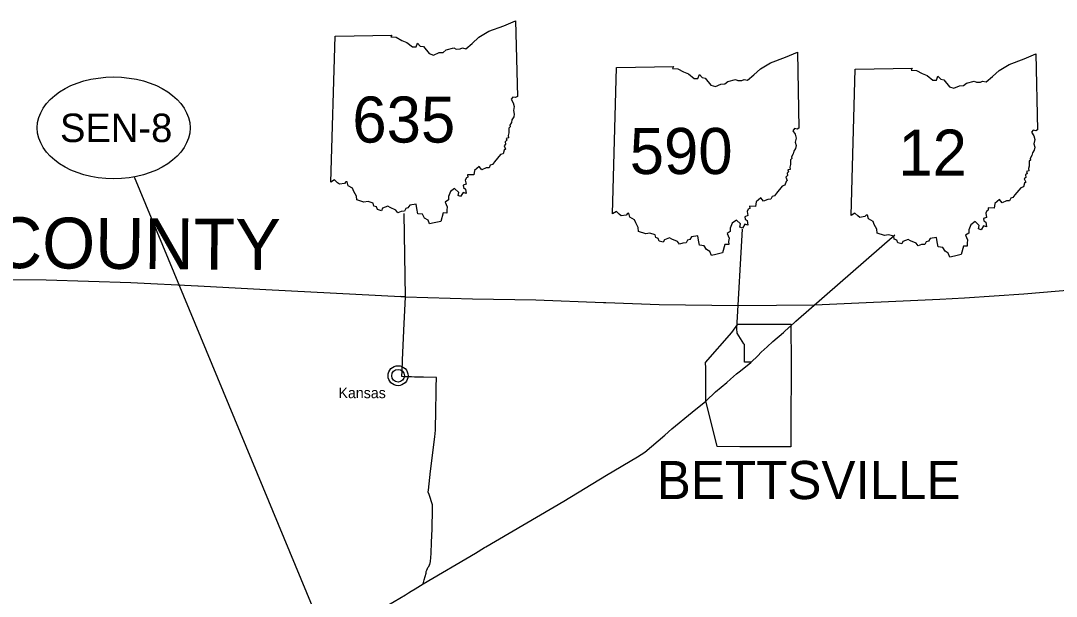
# Model space of a CAD drawing. Extents: x 0 to 882, y 0 to 440.
# Drawn here: x 198.3 to 300, y 305.2 to 361.8 of the extents above; entities that cross this region are included whole.
import ezdxf

# ---------------------------------------------------------------- set-up
doc = ezdxf.new("R2010")
doc.units = 0
for name, color, linetype in [('DV_X_Corp_Line', 7, 'Continuous'), ('GM_X_Adjacent_County_Text', 7, 'Continuous'), ('GM_X_Corporation_Text', 7, 'Continuous'), ('GM_X_County', 7, 'Continuous'), ('GM_X_State_Route', 7, 'Continuous'), ('PV_P_Text', 7, 'Continuous'), ('SH_Data', 7, 'Continuous')]:
    doc.layers.add(name, color=color, linetype=linetype)

msp = doc.modelspace()

# ---------------------------------------------------------------- linework, layer by layer
at = {"layer": 'DV_X_Corp_Line'}
msp.add_lwpolyline([(268.15, 331.12), (268.71, 331.93), (273.95, 331.93), (273.94, 331.71), (273.95, 328.22), (273.93, 321.61), (273.92, 319.86), (268.93, 319.88), (266.71, 319.91), (265.57, 324.39), (265.57, 327.61), (265.56, 328.17)], close=True, dxfattribs=at)
for radius in [0.982, 0.623]:
    msp.add_circle((235.37, 326.86), radius, dxfattribs=at)
at = {"layer": 'GM_X_County'}
msp.add_lwpolyline([(194.2, 336.33), (200.83, 336.27), (209.14, 336.02), (215.71, 335.69), (215.76, 335.68), (222.4, 335.32), (235.64, 334.64), (236.1, 334.62), (242.69, 334.42), (248.88, 334.31), (255.53, 334.06), (255.76, 334.05), (260.99, 333.86), (268.76, 333.76), (276.28, 333.83), (288.57, 334.37), (290.97, 334.51), (296.79, 334.89), (301.81, 335.33)], dxfattribs=at)
at = {"layer": 'GM_X_State_Route'}
msp.add_line((236.1, 334.62), (235.98, 342.8), dxfattribs=at)
for points in [[(268.63, 331.49), (268.63, 331.51), (269.18, 341.26)], [(274.42, 332.22), (284.15, 340.7)], [(235.74, 326.91), (235.76, 327.2), (235.78, 327.6), (235.78, 327.71), (235.79, 328), (235.81, 328.39), (235.92, 331.3), (236.1, 334.62), (235.64, 334.64)], [(270.03, 328.19), (269.39, 328.2), (269.39, 329.84), (269.38, 329.91), (269.33, 329.99), (268.66, 331.04), (268.63, 331.49)], [(271.62, 329.71), (272.16, 330.21), (273.21, 331.11), (273.81, 331.66), (273.85, 331.69)], [(273.85, 331.69), (274.39, 332.18), (274.42, 332.22)], [(270.68, 328.82), (271.03, 329.17), (271.62, 329.71)], [(270.03, 328.19), (270.68, 328.82)], [(268, 326.51), (268.61, 327.03), (268.86, 327.23), (269.31, 327.6)], [(269.31, 327.6), (270, 328.16), (270.03, 328.19)], [(239.12, 325.72), (239.15, 326.67), (237.87, 326.71), (237.59, 326.71), (237.29, 326.72), (236.98, 326.73), (236.68, 326.74), (236.41, 326.75), (236.08, 326.76), (235.74, 326.77), (235.74, 326.91)], [(265.63, 324.4), (266.53, 325.26), (267.64, 326.2), (268, 326.51)], [(237.85, 306.39), (237.92, 306.79), (238.12, 307.45), (238.14, 307.6), (238.18, 307.75), (238.26, 307.91), (238.29, 308), (238.38, 308.09), (238.43, 308.19), (238.49, 308.3), (238.57, 308.59), (238.63, 309.39), (238.65, 310.51), (238.71, 311.77), (238.75, 313.76), (238.75, 314.18), (238.7, 314.37), (238.49, 314.99), (238.41, 315.19), (238.34, 315.4), (238.34, 315.46), (238.35, 315.6), (238.57, 317.48), (238.97, 320.85), (239.03, 321.5), (239.05, 322.02), (239.08, 322.99), (239.12, 325.65), (239.12, 325.72)], [(243.86, 309.96), (243.97, 310.03), (251.64, 314.54), (255.82, 317.07), (258.88, 318.87), (259.61, 319.34), (261.55, 321), (262.26, 321.65), (264.25, 323.26), (265.59, 324.36), (265.63, 324.4)], [(236.65, 305.67), (237.06, 305.92), (237.85, 306.39), (242.96, 309.4), (243.86, 309.96)], [(218.84, 295.17), (218.85, 295.17), (221.01, 296.41), (221.46, 296.67), (228.35, 300.67), (232.56, 303.24), (234.98, 304.67), (236.1, 305.33), (236.39, 305.51), (236.65, 305.67)]]:
    msp.add_lwpolyline(points, dxfattribs=at)
at = {"layer": 'PV_P_Text'}
for p, q in [((228.77, 345.88), (229.18, 360.24)), ((228.77, 345.88), (229.18, 360.24)), ((256.43, 342.78), (256.83, 357.14)), ((256.43, 342.78), (256.83, 357.14)), ((279.86, 342.62), (280.26, 356.98)), ((279.86, 342.62), (280.26, 356.98))]:
    msp.add_line(p, q, dxfattribs=at)
for points in [[(229.18, 360.24), (234.75, 360.33), (234.66, 360.16), (235.19, 360.12), (235.75, 359.82), (236.22, 359.62), (236.8, 359.17), (237.14, 359.17), (237.29, 359.55), (237.55, 359.26), (237.87, 359.21), (238.41, 358.52), (238.86, 358.37), (239.4, 358.61), (239.8, 358.64), (240.09, 358.88), (240.85, 359.08), (241.07, 358.96), (241.47, 358.98), (241.68, 359.07), (242.03, 358.99), (242.65, 359.51), (243.29, 360.13), (244.28, 360.71), (245.75, 361.26), (246.91, 361.75), (247.08, 354.3)], [(229.18, 360.24), (234.75, 360.33), (234.66, 360.16), (235.19, 360.12), (235.75, 359.82), (236.22, 359.62), (236.8, 359.17), (237.14, 359.17), (237.29, 359.55), (237.55, 359.26), (237.87, 359.21), (238.41, 358.52), (238.86, 358.37), (239.4, 358.61), (239.8, 358.64), (240.09, 358.88), (240.85, 359.08), (241.07, 358.96), (241.47, 358.98), (241.68, 359.07), (242.03, 358.99), (242.65, 359.51), (243.29, 360.13), (244.28, 360.71), (245.75, 361.26), (246.91, 361.75), (247.08, 354.3)], [(256.83, 357.14), (262.41, 357.24), (262.32, 357.06), (262.85, 357.03), (263.4, 356.72), (263.88, 356.53), (264.45, 356.07), (264.8, 356.08), (264.95, 356.45), (265.21, 356.16), (265.53, 356.11), (266.07, 355.42), (266.52, 355.27), (267.05, 355.51), (267.46, 355.55), (267.75, 355.78), (268.51, 355.98), (268.73, 355.86), (269.13, 355.88), (269.34, 355.97), (269.69, 355.89), (270.31, 356.42), (270.95, 357.03), (271.93, 357.61), (273.4, 358.16), (274.57, 358.66), (274.73, 351.2)], [(256.83, 357.14), (262.41, 357.24), (262.32, 357.06), (262.85, 357.03), (263.4, 356.72), (263.88, 356.53), (264.45, 356.07), (264.8, 356.08), (264.95, 356.45), (265.21, 356.16), (265.53, 356.11), (266.07, 355.42), (266.52, 355.27), (267.05, 355.51), (267.46, 355.55), (267.75, 355.78), (268.51, 355.98), (268.73, 355.86), (269.13, 355.88), (269.34, 355.97), (269.69, 355.89), (270.31, 356.42), (270.95, 357.03), (271.93, 357.61), (273.4, 358.16), (274.57, 358.66), (274.73, 351.2)], [(280.26, 356.98), (285.83, 357.08), (285.75, 356.9), (286.27, 356.87), (286.83, 356.56), (287.3, 356.37), (287.88, 355.91), (288.23, 355.91), (288.37, 356.29), (288.64, 356), (288.95, 355.95), (289.5, 355.26), (289.94, 355.11), (290.48, 355.35), (290.88, 355.39), (291.18, 355.62), (291.94, 355.82), (292.15, 355.7), (292.56, 355.72), (292.76, 355.81), (293.12, 355.73), (293.74, 356.25), (294.38, 356.87), (295.36, 357.45), (296.83, 358), (297.99, 358.49), (298.16, 351.04)], [(280.26, 356.98), (285.83, 357.08), (285.75, 356.9), (286.27, 356.87), (286.83, 356.56), (287.3, 356.37), (287.88, 355.91), (288.23, 355.91), (288.37, 356.29), (288.64, 356), (288.95, 355.95), (289.5, 355.26), (289.94, 355.11), (290.48, 355.35), (290.88, 355.39), (291.18, 355.62), (291.94, 355.82), (292.15, 355.7), (292.56, 355.72), (292.76, 355.81), (293.12, 355.73), (293.74, 356.25), (294.38, 356.87), (295.36, 357.45), (296.83, 358), (297.99, 358.49), (298.16, 351.04)], [(247.08, 354.3), (246.9, 354.19), (246.64, 354.24), (246.46, 354.03), (246.68, 353.69), (246.78, 353.32), (246.69, 352.91), (246.78, 352.58), (246.72, 352.3), (246.55, 352.02), (246.5, 351.75), (246.35, 351.47), (246.36, 351.31), (246.23, 351.19), (246.25, 350.72), (246.18, 350.46), (246.21, 350.24), (245.99, 350.18), (246.04, 350), (245.9, 349.86), (245.93, 349.61), (245.77, 349.46), (245.92, 349.14), (245.8, 349.04), (245.7, 348.66), (245.41, 348.59), (244.85, 347.89), (244.65, 347.63), (244.42, 347.56), (244.3, 347.29), (244.02, 347.29), (243.6, 347.1), (243.33, 347.43), (242.86, 347.04), (242.8, 346.59), (242.2, 346.61), (242.23, 346.38), (242.09, 346.31), (241.97, 346.09), (242.04, 345.68), (241.76, 345.58), (241.8, 345.35), (241.98, 345.2), (242.06, 344.76), (241.76, 344.85), (241.51, 344.47), (241.26, 344.56), (241.34, 344.88), (240.92, 345.26), (240.52, 344.95), (240.31, 344.46), (240.31, 344.13), (240.01, 343.93), (240.2, 343.46), (240.16, 343.14), (240.17, 342.84), (239.79, 342.85), (239.57, 342.02)], [(247.08, 354.3), (246.9, 354.19), (246.64, 354.24), (246.46, 354.03), (246.68, 353.69), (246.78, 353.32), (246.69, 352.91), (246.78, 352.58), (246.72, 352.3), (246.55, 352.02), (246.5, 351.75), (246.35, 351.47), (246.36, 351.31), (246.23, 351.19), (246.25, 350.72), (246.18, 350.46), (246.21, 350.24), (245.99, 350.18), (246.04, 350), (245.9, 349.86), (245.93, 349.61), (245.77, 349.46), (245.92, 349.14), (245.8, 349.04), (245.7, 348.66), (245.41, 348.59), (244.85, 347.89), (244.65, 347.63), (244.42, 347.56), (244.3, 347.29), (244.02, 347.29), (243.6, 347.1), (243.33, 347.43), (242.86, 347.04), (242.8, 346.59), (242.2, 346.61), (242.23, 346.38), (242.09, 346.31), (241.97, 346.09), (242.04, 345.68), (241.76, 345.58), (241.8, 345.35), (241.98, 345.2), (242.06, 344.76), (241.76, 344.85), (241.51, 344.47), (241.26, 344.56), (241.34, 344.88), (240.92, 345.26), (240.52, 344.95), (240.31, 344.46), (240.31, 344.13), (240.01, 343.93), (240.2, 343.46), (240.16, 343.14), (240.17, 342.84), (239.79, 342.85), (239.57, 342.02)], [(274.73, 351.2), (274.56, 351.1), (274.3, 351.15), (274.12, 350.94), (274.34, 350.59), (274.44, 350.22), (274.35, 349.81), (274.44, 349.48), (274.38, 349.2), (274.21, 348.92), (274.15, 348.65), (274.01, 348.37), (274.02, 348.22), (273.89, 348.09), (273.91, 347.63), (273.84, 347.37), (273.87, 347.14), (273.65, 347.09), (273.7, 346.9), (273.56, 346.76), (273.59, 346.52), (273.43, 346.36), (273.58, 346.05), (273.46, 345.95), (273.35, 345.57), (273.07, 345.49), (272.51, 344.79), (272.31, 344.53), (272.08, 344.47), (271.96, 344.2), (271.68, 344.19), (271.26, 344.01), (270.99, 344.33), (270.52, 343.94), (270.46, 343.49), (269.86, 343.51), (269.89, 343.28), (269.75, 343.22), (269.63, 342.99), (269.7, 342.59), (269.42, 342.48), (269.45, 342.25), (269.63, 342.11), (269.71, 341.66), (269.42, 341.75), (269.17, 341.37), (268.92, 341.46), (269, 341.78), (268.58, 342.16), (268.18, 341.86), (267.97, 341.37), (267.96, 341.03), (267.67, 340.84), (267.86, 340.37), (267.82, 340.05), (267.83, 339.74), (267.45, 339.75), (267.23, 338.93)], [(274.73, 351.2), (274.56, 351.1), (274.3, 351.15), (274.12, 350.94), (274.34, 350.59), (274.44, 350.22), (274.35, 349.81), (274.44, 349.48), (274.38, 349.2), (274.21, 348.92), (274.15, 348.65), (274.01, 348.37), (274.02, 348.22), (273.89, 348.09), (273.91, 347.63), (273.84, 347.37), (273.87, 347.14), (273.65, 347.09), (273.7, 346.9), (273.56, 346.76), (273.59, 346.52), (273.43, 346.36), (273.58, 346.05), (273.46, 345.95), (273.35, 345.57), (273.07, 345.49), (272.51, 344.79), (272.31, 344.53), (272.08, 344.47), (271.96, 344.2), (271.68, 344.19), (271.26, 344.01), (270.99, 344.33), (270.52, 343.94), (270.46, 343.49), (269.86, 343.51), (269.89, 343.28), (269.75, 343.22), (269.63, 342.99), (269.7, 342.59), (269.42, 342.48), (269.45, 342.25), (269.63, 342.11), (269.71, 341.66), (269.42, 341.75), (269.17, 341.37), (268.92, 341.46), (269, 341.78), (268.58, 342.16), (268.18, 341.86), (267.97, 341.37), (267.96, 341.03), (267.67, 340.84), (267.86, 340.37), (267.82, 340.05), (267.83, 339.74), (267.45, 339.75), (267.23, 338.93)], [(298.16, 351.04), (297.99, 350.94), (297.72, 350.98), (297.54, 350.78), (297.77, 350.43), (297.87, 350.06), (297.78, 349.65), (297.87, 349.32), (297.81, 349.04), (297.64, 348.76), (297.58, 348.49), (297.44, 348.21), (297.45, 348.05), (297.31, 347.93), (297.34, 347.46), (297.27, 347.21), (297.29, 346.98), (297.07, 346.92), (297.12, 346.74), (296.98, 346.6), (297.01, 346.35), (296.85, 346.2), (297.01, 345.88), (296.88, 345.79), (296.78, 345.41), (296.5, 345.33), (295.93, 344.63), (295.73, 344.37), (295.51, 344.3), (295.38, 344.03), (295.11, 344.03), (294.69, 343.85), (294.42, 344.17), (293.94, 343.78), (293.89, 343.33), (293.29, 343.35), (293.31, 343.12), (293.18, 343.05), (293.06, 342.83), (293.13, 342.42), (292.85, 342.32), (292.88, 342.09), (293.06, 341.94), (293.14, 341.5), (292.84, 341.59), (292.6, 341.21), (292.35, 341.3), (292.43, 341.62), (292.01, 342), (291.6, 341.7), (291.39, 341.2), (291.39, 340.87), (291.09, 340.67), (291.28, 340.21), (291.25, 339.88), (291.25, 339.58), (290.88, 339.59), (290.65, 338.77)], [(298.16, 351.04), (297.99, 350.94), (297.72, 350.98), (297.54, 350.78), (297.77, 350.43), (297.87, 350.06), (297.78, 349.65), (297.87, 349.32), (297.81, 349.04), (297.64, 348.76), (297.58, 348.49), (297.44, 348.21), (297.45, 348.05), (297.31, 347.93), (297.34, 347.46), (297.27, 347.21), (297.29, 346.98), (297.07, 346.92), (297.12, 346.74), (296.98, 346.6), (297.01, 346.35), (296.85, 346.2), (297.01, 345.88), (296.88, 345.79), (296.78, 345.41), (296.5, 345.33), (295.93, 344.63), (295.73, 344.37), (295.51, 344.3), (295.38, 344.03), (295.11, 344.03), (294.69, 343.85), (294.42, 344.17), (293.94, 343.78), (293.89, 343.33), (293.29, 343.35), (293.31, 343.12), (293.18, 343.05), (293.06, 342.83), (293.13, 342.42), (292.85, 342.32), (292.88, 342.09), (293.06, 341.94), (293.14, 341.5), (292.84, 341.59), (292.6, 341.21), (292.35, 341.3), (292.43, 341.62), (292.01, 342), (291.6, 341.7), (291.39, 341.2), (291.39, 340.87), (291.09, 340.67), (291.28, 340.21), (291.25, 339.88), (291.25, 339.58), (290.88, 339.59), (290.65, 338.77)], [(239.57, 342.02), (238.92, 341.87), (238.47, 341.77), (238.31, 342.15), (237.98, 342.34), (237.77, 342.72), (237.31, 342.77), (237.2, 343.29), (237.15, 343.71), (236.52, 343.61), (236.34, 343.35), (236.12, 343.28), (235.99, 343.02), (235.68, 343), (235.35, 342.88), (235.14, 343.13), (234.6, 343.39), (234.35, 343.52), (233.85, 343.31), (233.74, 343.07), (233.34, 343.18), (233.24, 343.45), (233, 343.53), (232.94, 343.82), (232.42, 343.97), (232.02, 343.91), (231.32, 344.14), (231.28, 344.51), (231.04, 344.97), (230.91, 345.29), (230.47, 345.53), (230.38, 345.91), (230.24, 345.9), (230.11, 345.75), (229.61, 345.68), (229.42, 345.83), (229.14, 346.1), (228.77, 345.88)], [(239.57, 342.02), (238.92, 341.87), (238.47, 341.77), (238.31, 342.15), (237.98, 342.34), (237.77, 342.72), (237.31, 342.77), (237.2, 343.29), (237.15, 343.71), (236.52, 343.61), (236.34, 343.35), (236.12, 343.28), (235.99, 343.02), (235.68, 343), (235.35, 342.88), (235.14, 343.13), (234.6, 343.39), (234.35, 343.52), (233.85, 343.31), (233.74, 343.07), (233.34, 343.18), (233.24, 343.45), (233, 343.53), (232.94, 343.82), (232.42, 343.97), (232.02, 343.91), (231.32, 344.14), (231.28, 344.51), (231.04, 344.97), (230.91, 345.29), (230.47, 345.53), (230.38, 345.91), (230.24, 345.9), (230.11, 345.75), (229.61, 345.68), (229.42, 345.83), (229.14, 346.1), (228.77, 345.88)], [(267.23, 338.93), (266.58, 338.77), (266.13, 338.67), (265.97, 339.05), (265.64, 339.25), (265.43, 339.62), (264.97, 339.68), (264.86, 340.19), (264.81, 340.61), (264.17, 340.51), (264, 340.25), (263.78, 340.18), (263.65, 339.93), (263.34, 339.9), (263.01, 339.78), (262.79, 340.04), (262.26, 340.29), (262.01, 340.42), (261.51, 340.22), (261.4, 339.98), (261, 340.08), (260.9, 340.35), (260.66, 340.43), (260.6, 340.72), (260.08, 340.87), (259.68, 340.81), (258.98, 341.04), (258.94, 341.42), (258.7, 341.88), (258.57, 342.19), (258.13, 342.44), (258.04, 342.82), (257.9, 342.81), (257.77, 342.65), (257.27, 342.58), (257.07, 342.74), (256.8, 343), (256.43, 342.78)], [(267.23, 338.93), (266.58, 338.77), (266.13, 338.67), (265.97, 339.05), (265.64, 339.25), (265.43, 339.62), (264.97, 339.68), (264.86, 340.19), (264.81, 340.61), (264.17, 340.51), (264, 340.25), (263.78, 340.18), (263.65, 339.93), (263.34, 339.9), (263.01, 339.78), (262.79, 340.04), (262.26, 340.29), (262.01, 340.42), (261.51, 340.22), (261.4, 339.98), (261, 340.08), (260.9, 340.35), (260.66, 340.43), (260.6, 340.72), (260.08, 340.87), (259.68, 340.81), (258.98, 341.04), (258.94, 341.42), (258.7, 341.88), (258.57, 342.19), (258.13, 342.44), (258.04, 342.82), (257.9, 342.81), (257.77, 342.65), (257.27, 342.58), (257.07, 342.74), (256.8, 343), (256.43, 342.78)], [(290.65, 338.77), (290, 338.61), (289.55, 338.51), (289.39, 338.89), (289.07, 339.09), (288.86, 339.46), (288.4, 339.51), (288.29, 340.03), (288.24, 340.45), (287.6, 340.35), (287.43, 340.09), (287.2, 340.02), (287.07, 339.76), (286.77, 339.74), (286.44, 339.62), (286.22, 339.87), (285.68, 340.13), (285.44, 340.26), (284.93, 340.06), (284.83, 339.81), (284.42, 339.92), (284.33, 340.19), (284.08, 340.27), (284.03, 340.56), (283.51, 340.71), (283.11, 340.65), (282.41, 340.88), (282.36, 341.26), (282.12, 341.71), (282, 342.03), (281.55, 342.28), (281.46, 342.65), (281.32, 342.64), (281.19, 342.49), (280.7, 342.42), (280.5, 342.57), (280.22, 342.84), (279.86, 342.62)], [(290.65, 338.77), (290, 338.61), (289.55, 338.51), (289.39, 338.89), (289.07, 339.09), (288.86, 339.46), (288.4, 339.51), (288.29, 340.03), (288.24, 340.45), (287.6, 340.35), (287.43, 340.09), (287.2, 340.02), (287.07, 339.76), (286.77, 339.74), (286.44, 339.62), (286.22, 339.87), (285.68, 340.13), (285.44, 340.26), (284.93, 340.06), (284.83, 339.81), (284.42, 339.92), (284.33, 340.19), (284.08, 340.27), (284.03, 340.56), (283.51, 340.71), (283.11, 340.65), (282.41, 340.88), (282.36, 341.26), (282.12, 341.71), (282, 342.03), (281.55, 342.28), (281.46, 342.65), (281.32, 342.64), (281.19, 342.49), (280.7, 342.42), (280.5, 342.57), (280.22, 342.84), (279.86, 342.62)]]:
    msp.add_lwpolyline(points, dxfattribs=at)
at = {"layer": 'SH_Data'}
msp.add_line((209.45, 346.4), (234.84, 285.18), dxfattribs=at)
msp.add_ellipse((207.45, 351.22), major_axis=(7.5, 0), ratio=0.666667, dxfattribs=at)

# ---------------------------------------------------------------- texts
at = {"layer": 'DV_X_Corp_Line'}
msp.add_text('Kansas', height=1.042, rotation=0, dxfattribs=at).set_placement((229.52, 324.65))
at = {"layer": 'GM_X_Adjacent_County_Text'}
msp.add_text('SANDUSKY COUNTY', height=5, rotation=359.5945, dxfattribs=at).set_placement((156.95, 337.72))
at = {"layer": 'GM_X_Corporation_Text'}
msp.add_text('BETTSVILLE', height=3.75, rotation=0, dxfattribs=at).set_placement((260.77, 314.73))
at = {"layer": 'PV_P_Text'}
for s, p in [('635', (230.88, 349.77)), ('590', (258.11, 346.68)), ('12', (284.48, 346.52))]:
    msp.add_text(s, height=4.528, dxfattribs=at).set_placement(p)
at = {"layer": 'SH_Data'}
msp.add_text('SEN-8', height=2.8, dxfattribs=at).set_placement((202.18, 349.82))

doc.saveas('drawing.dxf')
